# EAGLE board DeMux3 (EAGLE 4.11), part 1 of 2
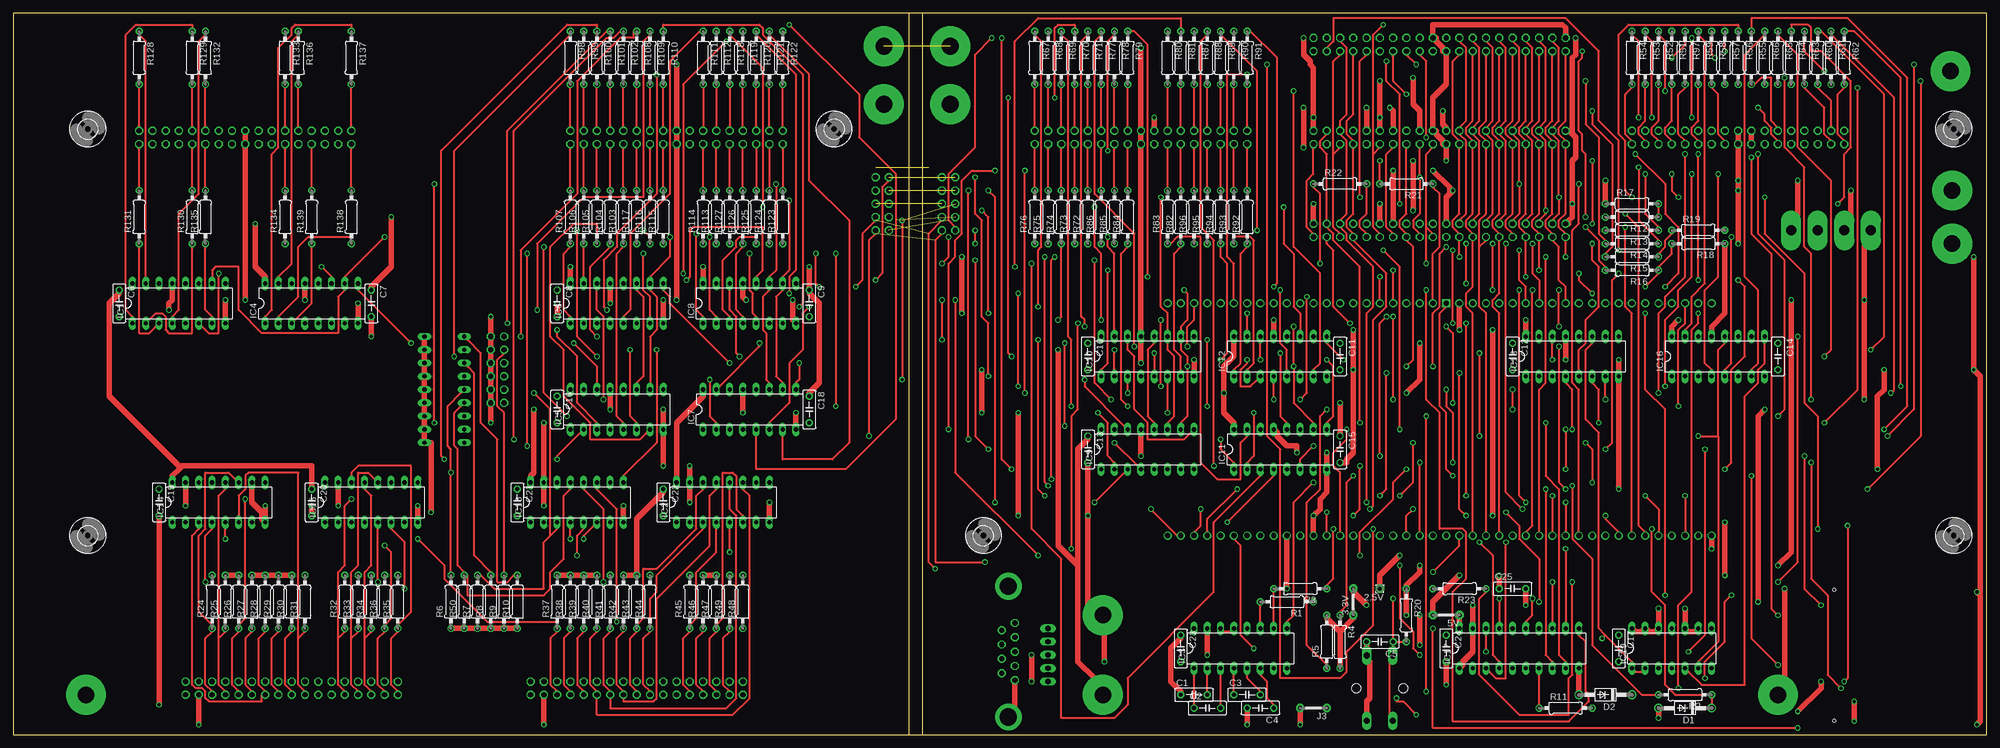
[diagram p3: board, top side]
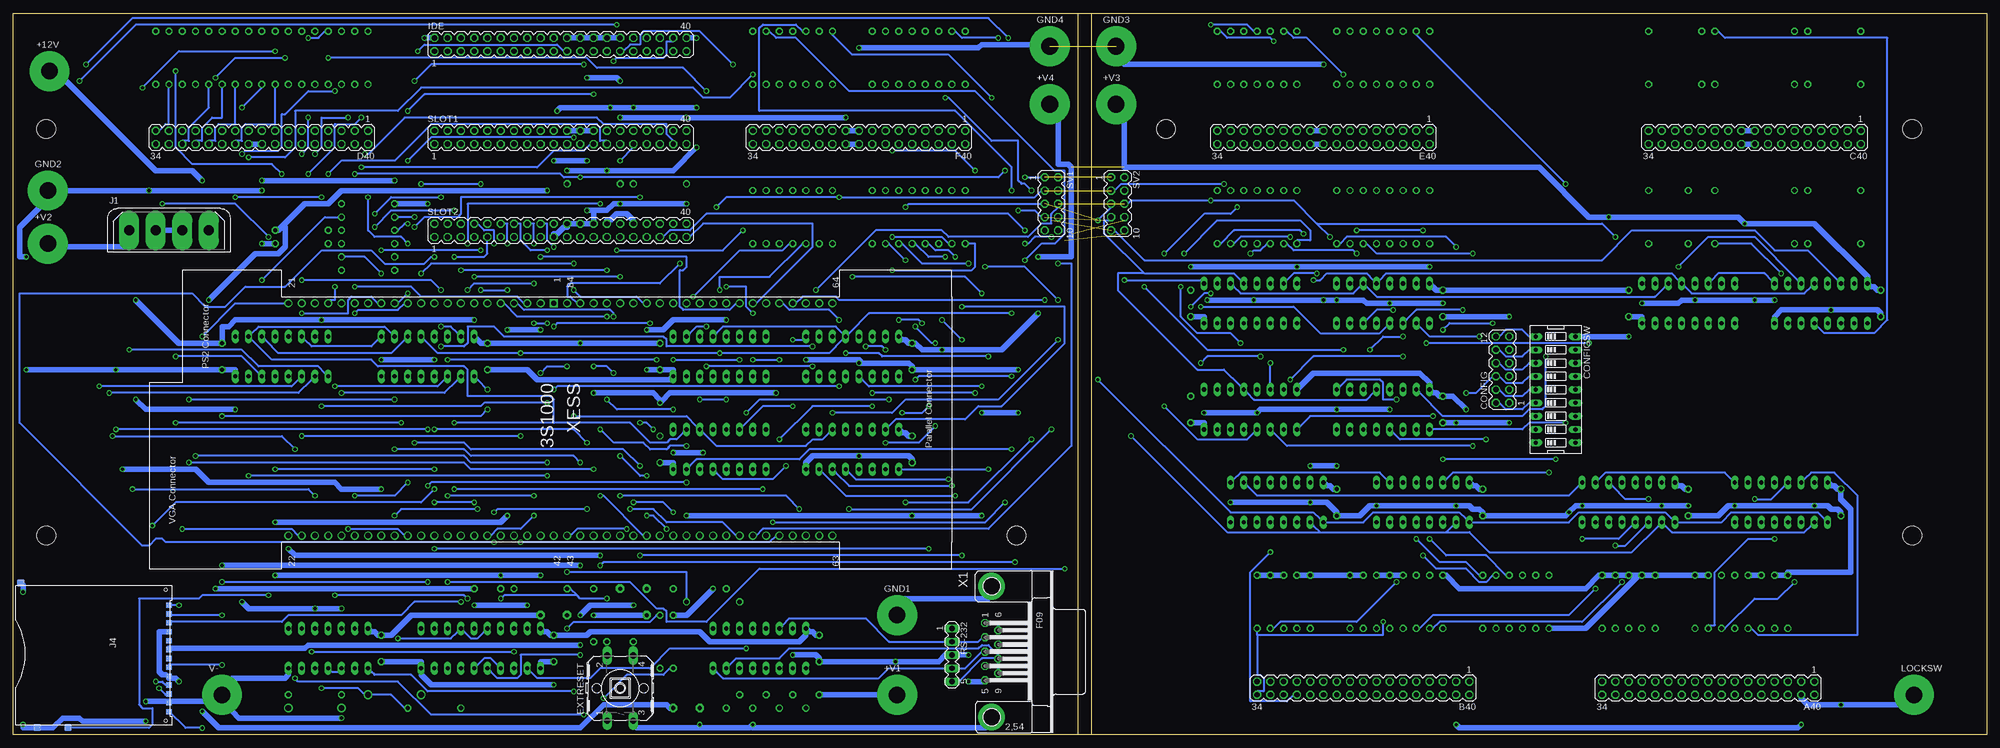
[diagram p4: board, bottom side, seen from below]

Size 377.82 x 138.11 mm. Coordinates in mm from the lower left corner, seen from the top.
Outline: 377.82,138.11 377.82,0 174.62,0 171.45,0
Outline: 377.82,138.11 173.99,138.11
Outline: 173.99,138.11 173.04,138.11
Outline: 173.04,138.11 171.45,138.11
Outline: 171.45,138.11 0,138.11 0,0 171.45,0
Outline: 377.82,138.11 173.99,138.11
Outline: 173.99,138.11 173.04,138.11
Outline: 171.45,138.11 171.45,0
Outline: 173.99,138.11 173.99,0
Copper layers (1*16): Top 0.035mm / dielectric 1.5mm / Bottom 0.035mm
Design rules "15mils": minimum track width 15mil, minimum drill 24mil, track to track 15mil, track to pad 10mil, pad to pad 10mil, via to via 10mil, smd to smd 10mil, copper to edge 25mil, drill to drill 10mil, minimum pad ring 10mil, minimum via ring 8mil, stop-mask expansion 0mil, vias tented up to drill 0mil, thermal gap 10mil
Net classes: 1 supply: width 1.016 mm

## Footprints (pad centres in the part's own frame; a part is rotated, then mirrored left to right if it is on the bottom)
1,6/0,8 = drill 0.813 pad 1.6 octagon: 1 0,0
05 = drill 0.813 pad 1.6 octagon: 1 -2.54,0; 2 2.54,0
SPADELUG = drill 3.175 pad 7.62 round: 1 0,0
MA17-2 = drill 1.016 octagon: 1 -20.32,-1.27; 2 -20.32,1.27; 3 -17.78,-1.27; 4 -17.78,1.27; 5 -15.24,-1.27; 6 -15.24,1.27; 7 -12.7,-1.27; 8 -12.7,1.27; 9 -10.16,-1.27; 10 -10.16,1.27; 11 -7.62,-1.27; 12 -7.62,1.27; 13 -5.08,-1.27; 14 -5.08,1.27; 15 -2.54,-1.27; 16 -2.54,1.27; 17 0,-1.27; 18 0,1.27; 19 2.54,-1.27; 20 2.54,1.27; 21 5.08,-1.27; 22 5.08,1.27; 23 7.62,-1.27; 24 7.62,1.27; 25 10.16,-1.27; 26 10.16,1.27; 27 12.7,-1.27; 28 12.7,1.27; 29 15.24,-1.27; 30 15.24,1.27; 31 17.78,-1.27; 32 17.78,1.27; 33 20.32,-1.27; 34 20.32,1.27
C050-025X075 = drill 0.813 octagon: 1 -2.54,0; 2 2.54,0
MA06-2 = drill 1.016 octagon: 1 -6.35,-1.27; 2 -6.35,1.27; 3 -3.81,-1.27; 4 -3.81,1.27; 5 -1.27,-1.27; 6 -1.27,1.27; 7 1.27,-1.27; 8 1.27,1.27; 9 3.81,-1.27; 10 3.81,1.27; 11 6.35,-1.27; 12 6.35,1.27
EDG-09 = drill 0.813 long: 1 -10.16,-3.81; 2 -7.62,-3.81; 3 -5.08,-3.81; 4 -2.54,-3.81; 5 0,-3.81; 6 2.54,-3.81; 7 5.08,-3.81; 8 7.62,-3.81; 9 10.16,-3.81; 10 10.16,3.81; 11 7.62,3.81; 12 5.08,3.81; 13 2.54,3.81; 14 0,3.81; 15 -2.54,3.81; 16 -5.08,3.81; 17 -7.62,3.81; 18 -10.16,3.81
DO41Z10 = drill 1.118 round: A 5.08,0; C -5.08,0
B3F-40XX = drill 1.194 long: 1 -6.248,2.489; 2 6.248,2.489; 3 -6.248,-2.489; 4 6.248,-2.489 | hole 1.803: 0,-4.496; 0,4.496
DIL16 = drill 0.813 long: 1 -8.89,-3.81; 2 -6.35,-3.81; 3 -3.81,-3.81; 4 -1.27,-3.81; 5 1.27,-3.81; 6 3.81,-3.81; 7 6.35,-3.81; 8 8.89,-3.81; 9 8.89,3.81; 10 6.35,3.81; 11 3.81,3.81; 12 1.27,3.81; 13 -1.27,3.81; 14 -3.81,3.81; 15 -6.35,3.81; 16 -8.89,3.81
DIL20 = drill 0.813 long: 1 -11.43,-3.81; 2 -8.89,-3.81; 3 -6.35,-3.81; 4 -3.81,-3.81; 5 -1.27,-3.81; 6 1.27,-3.81; 7 3.81,-3.81; 8 6.35,-3.81; 9 8.89,-3.81; 10 11.43,-3.81; 11 11.43,3.81; 12 8.89,3.81; 13 6.35,3.81; 14 3.81,3.81; 15 1.27,3.81; 16 -1.27,3.81; 17 -3.81,3.81; 18 -6.35,3.81; 19 -8.89,3.81; 20 -11.43,3.81
DIL14 = drill 0.813 long: 1 -7.62,-3.81; 2 -5.08,-3.81; 3 -2.54,-3.81; 4 0,-3.81; 5 2.54,-3.81; 6 5.08,-3.81; 7 7.62,-3.81; 8 7.62,3.81; 9 5.08,3.81; 10 2.54,3.81; 11 0,3.81; 12 -2.54,3.81; 13 -5.08,3.81; 14 -7.62,3.81
MA20-2 = drill 1.016 octagon: 1 -24.13,-1.27; 2 -24.13,1.27; 3 -21.59,-1.27; 4 -21.59,1.27; 5 -19.05,-1.27; 6 -19.05,1.27; 7 -16.51,-1.27; 8 -16.51,1.27; 9 -13.97,-1.27; 10 -13.97,1.27; 11 -11.43,-1.27; 12 -11.43,1.27; 13 -8.89,-1.27; 14 -8.89,1.27; 15 -6.35,-1.27; 16 -6.35,1.27; 17 -3.81,-1.27; 18 -3.81,1.27; 19 -1.27,-1.27; 20 -1.27,1.27; 21 1.27,-1.27; 22 1.27,1.27; 23 3.81,-1.27; 24 3.81,1.27; 25 6.35,-1.27; 26 6.35,1.27; 27 8.89,-1.27; 28 8.89,1.27; 29 11.43,-1.27; 30 11.43,1.27; 31 13.97,-1.27; 32 13.97,1.27; 33 16.51,-1.27; 34 16.51,1.27; 35 19.05,-1.27; 36 19.05,1.27; 37 21.59,-1.27; 38 21.59,1.27; 39 24.13,-1.27; 40 24.13,1.27
FLOPPY-4 = drill 1.93 pad 3.81 long: 1 7.62,0; 2 2.54,0; 3 -2.54,0; 4 -7.62,0
SCDA5A = smd 1 x 1.3: 1 -7.525,-0.65; 2 -5.825,-0.65; 3 -4.125,-0.65; 3A -2.425,-0.65; 4 -0.725,-0.65; 4A 0.975,-0.65; 5 2.675,-0.65; 6 4.375,-0.65; 7 6.075,-0.65; 8 7.775,-0.65; 9 -9.225,-0.65; 10 11.175,-0.65; 11 9.475,-0.65 | smd 1.4 x 1.4: 12 14.2,-19.955; 13 14.2,-25.875; 14 -13.475,-28.975 | hole 0.61: 12.875,-1.235; -12.125,-1.235
0207/10 = drill 0.813 octagon: 1 -5.08,0; 2 5.08,0
MA05-1 = drill 1.016 long: 1 -5.08,0; 2 -2.54,0; 3 0,0; 4 2.54,0; 5 5.08,0
MA05-2 = drill 1.016 octagon: 1 -5.08,-1.27; 2 -5.08,1.27; 3 -2.54,-1.27; 4 -2.54,1.27; 5 0,-1.27; 6 0,1.27; 7 2.54,-1.27; 8 2.54,1.27; 9 5.08,-1.27; 10 5.08,1.27
3,6 = hole 3.6: 0,0
F09HP = drill 1.016 octagon: 1 -5.486,-1.27; 2 -2.743,-1.27; 3 0,-1.27; 4 2.743,-1.27; 5 5.486,-1.27; 6 -4.115,1.27; 7 -1.372,1.27; 8 1.372,1.27; 9 4.115,1.27 | drill 3.302 pad 5.08 round: G1 -12.522,0; G2 12.522,0
3S1000 = drill 1.016 square: 1 0,0 | drill 1.016 round: 2 0,-2.54; 3 0,-5.08; 4 0,-7.62; 5 0,-10.16; 6 0,-12.7; 7 0,-15.24; 8 0,-17.78; 9 0,-20.32; 10 0,-22.86; 11 0,-25.4; 12 0,-27.94; 13 0,-30.48; 14 0,-33.02; 15 0,-35.56; 16 0,-38.1; 17 0,-40.64; 18 0,-43.18; 19 0,-45.72; 20 0,-48.26; 21 0,-50.8; 22 44.45,-50.8; 23 44.45,-48.26; 24 44.45,-45.72; 25 44.45,-43.18; 26 44.45,-40.64; 27 44.45,-38.1; 28 44.45,-35.56; 29 44.45,-33.02; 30 44.45,-30.48; 31 44.45,-27.94; 32 44.45,-25.4; 33 44.45,-22.86; 34 44.45,-20.32; 35 44.45,-17.78; 36 44.45,-15.24; 37 44.45,-12.7; 38 44.45,-10.16; 39 44.45,-7.62; 40 44.45,-5.08; 41 44.45,-2.54; 42 44.45,0; 43 44.45,2.54; 44 44.45,5.08; 45 44.45,7.62; 46 44.45,10.16; 47 44.45,12.7; 48 44.45,15.24; 49 44.45,17.78; 50 44.45,20.32; 51 44.45,22.86; 52 44.45,25.4; 53 44.45,27.94; 54 44.45,30.48; 55 44.45,33.02; 56 44.45,35.56; 57 44.45,38.1; 58 44.45,40.64; 59 44.45,43.18; 60 44.45,45.72; 61 44.45,48.26; 62 44.45,50.8; 63 44.45,53.34; 64 0,53.34; 65 0,50.8; 66 0,48.26; 67 0,45.72; 68 0,43.18; 69 0,40.64; 70 0,38.1; 71 0,35.56; 72 0,33.02; 73 0,30.48; 74 0,27.94; 75 0,25.4; 76 0,22.86; 77 0,20.32; 78 0,17.78; 79 0,15.24; 80 0,12.7; 81 0,10.16; 82 0,7.62; 83 0,5.08; 84 0,2.54

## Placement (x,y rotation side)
2.5V  [1,6/0,8]  261.62,27.94 180 top
3.3V  J5MM  [05]  256.54,25.4 90 top
5V  J5MM  [05]  274.32,22.86 180 top
+12V  LUG  [SPADELUG]  370.84,127 0 bottom
+V1  LUG  [SPADELUG]  208.6,7.62 0 bottom
+V2  LUG  [SPADELUG]  371.16,93.98 0 bottom
+V3  LUG  [SPADELUG]  166.69,120.65 0 bottom
+V4  LUG  [SPADELUG]  179.39,120.65 0 bottom
A40  [MA17-2]  53.34,8.89 180 bottom
B40  [MA17-2]  119.38,8.89 180 bottom
C1  0.1uf  [C050-025X075]  226.06,7.62 0 top
C2  0.1uf  [C050-025X075]  228.6,5.08 0 top
C3  0.1uf  [C050-025X075]  236.22,7.62 0 top
C4  0.1uf  [C050-025X075]  238.76,5.08 180 top
C5  0.1uf  [C050-025X075]  261.62,17.78 180 top
C6  0.1uf  [C050-025X075]  20.32,82.55 270 top
C7  0.1uf  [C050-025X075]  68.58,82.55 270 top
C8  0.1uf  [C050-025X075]  104.14,82.55 270 top
C9  0.1uf  [C050-025X075]  152.4,82.55 270 top
C10  0.1uf  [C050-025X075]  205.74,72.39 270 top
C11  0.1uf  [C050-025X075]  254,72.39 270 top
C12  0.1uf  [C050-025X075]  287.02,72.39 270 top
C13  0.1uf  [C050-025X075]  205.74,54.61 270 top
C14  0.1uf  [C050-025X075]  337.82,72.39 270 top
C15  0.1uf  [C050-025X075]  254,54.61 270 top
C16  0.1uf  [C050-025X075]  104.14,62.23 270 top
C17  0.1uf  [C050-025X075]  307.34,16.51 270 top
C18  0.1uf  [C050-025X075]  152.4,62.23 270 top
C19  0.1uf  [C050-025X075]  27.94,44.45 270 top
C20  0.1uf  [C050-025X075]  57.15,44.45 270 top
C21  0.1uf  [C050-025X075]  96.52,44.45 270 top
C22  0.1uf  [C050-025X075]  124.46,44.45 270 top
C23  0.1uf  [C050-025X075]  223.52,16.51 270 top
C24  0.1uf  [C050-025X075]  274.32,16.51 270 top
C25  0.1uf  [C050-025X075]  287.02,27.94 0 top
C40  [MA17-2]  44.45,114.3 180 bottom
CONFIG  [MA06-2]  92.71,69.85 90 bottom
CONFIGSW  [EDG-09]  82.55,66.04 270 bottom
D1  1N4728  [DO41Z10]  320.04,5.08 180 top
D2  1N4728  [DO41Z10]  304.8,7.62 180 top
D40  [MA17-2]  330.2,114.3 180 bottom
E40  [MA17-2]  127,114.3 180 bottom
EXTRESET  [B3F-40XX]  261.62,8.89 90 bottom
F40  [MA17-2]  215.9,114.3 180 bottom
GND1  LUG  [SPADELUG]  208.6,22.86 0 bottom
GND2  LUG  [SPADELUG]  371.16,104.14 0 bottom
GND3  LUG  [SPADELUG]  166.69,131.76 0 bottom
GND4  LUG  [SPADELUG]  179.39,131.76 0 bottom
IC1  74HC595N  [DIL16]  31.75,82.55 0 top
IC2  74HC165N  [DIL16]  135.89,44.45 0 top
IC3  MAX232A  [DIL16]  234.95,16.51 0 top
IC4  74HC595N  [DIL16]  57.15,82.55 0 top
IC5  74HC595N  [DIL16]  115.57,62.23 0 top
IC6  74HC595N  [DIL16]  115.57,82.55 0 top
IC7  74HC595N  [DIL16]  140.97,62.23 0 top
IC8  74HC595N  [DIL16]  140.97,82.55 0 top
IC9  74HC595N  [DIL16]  217.17,54.61 0 top
IC10  74HC595N  [DIL16]  217.17,72.39 0 top
IC11  74HC595N  [DIL16]  242.57,54.61 0 top
IC12  74HC595N  [DIL16]  242.57,72.39 0 top
IC13  74HC595N  [DIL16]  298.45,72.39 0 top
IC14  74HC165N  [DIL16]  39.37,44.45 0 top
IC15  74HC165N  [DIL16]  68.58,44.45 0 top
IC16  74HC595N  [DIL16]  326.39,72.39 0 top
IC17  74HCT244N  [DIL20]  288.29,16.51 0 top
IC18  74HC165N  [DIL16]  107.95,44.45 0 top
IC19  74ALS00N  [DIL14]  317.5,16.51 0 top
IDE  [MA20-2]  273.05,132.08 0 bottom
J1  [FLOPPY-4]  347.98,96.52 0 bottom
J3  J5MM  [05]  248.92,5.08 180 top
J4  SDCARD  [SCDA5A]  347.35,15.56 270 bottom
LOCKSW  LUG  [SPADELUG]  13.97,7.62 0 bottom
R1  330  [0207/10]  243.84,25.4 180 top
R2  330  [0207/10]  320.04,7.62 180 top
R3  330  [0207/10]  246.38,27.94 180 top
R4  330  [0207/10]  254,17.78 270 top
R5  330  [0207/10]  251.46,17.78 90 top
R6  3K  [0207/10]  83.82,25.4 90 top
R7  3K  [0207/10]  88.9,25.4 90 top
R8  3K  [0207/10]  91.44,25.4 90 top
R9  3K  [0207/10]  93.98,25.4 90 top
R10  3K  [0207/10]  96.52,25.4 90 top
R11  330  [0207/10]  297.18,5.08 0 top
R12  330  [0207/10]  309.88,99.06 180 top
R13  47  [0207/10]  309.88,96.52 180 top
R14  47  [0207/10]  309.88,93.98 180 top
R15  330  [0207/10]  309.88,91.44 180 top
R16  330  [0207/10]  309.88,88.9 180 top
R17  10K  [0207/10]  309.88,101.6 0 top
R18  10K  [0207/10]  322.58,93.98 180 top
R19  10K  [0207/10]  322.58,96.52 0 top
R20  4.7K  [0207/10]  266.7,22.86 270 top
R21  330  [0207/10]  266.7,105.41 180 top
R22  330  [0207/10]  254,105.41 0 top
R23  330  [0207/10]  276.86,27.94 180 top
R24  3K  [0207/10]  38.1,25.4 90 top
R25  3K  [0207/10]  40.64,25.4 90 top
R26  3K  [0207/10]  43.18,25.4 90 top
R27  3K  [0207/10]  45.72,25.4 90 top
R28  3K  [0207/10]  48.26,25.4 90 top
R29  3K  [0207/10]  50.8,25.4 90 top
R30  3K  [0207/10]  53.34,25.4 90 top
R31  3K  [0207/10]  55.88,25.4 90 top
R32  3K  [0207/10]  63.5,25.4 90 top
R33  3K  [0207/10]  66.04,25.4 90 top
R34  3K  [0207/10]  68.58,25.4 90 top
R35  3K  [0207/10]  73.66,25.4 90 top
R36  3K  [0207/10]  71.12,25.4 90 top
R37  3K  [0207/10]  104.14,25.4 90 top
R38  3K  [0207/10]  106.68,25.4 90 top
R39  3K  [0207/10]  109.22,25.4 90 top
R40  3K  [0207/10]  111.76,25.4 90 top
R41  3K  [0207/10]  114.3,25.4 90 top
R42  3K  [0207/10]  116.84,25.4 90 top
R43  3K  [0207/10]  119.38,25.4 90 top
R44  3K  [0207/10]  121.92,25.4 90 top
R45  3K  [0207/10]  129.54,25.4 90 top
R46  3K  [0207/10]  132.08,25.4 90 top
R47  3K  [0207/10]  134.62,25.4 90 top
R48  3K  [0207/10]  139.7,25.4 90 top
R49  3K  [0207/10]  137.16,25.4 90 top
R50  3K  [0207/10]  86.36,25.4 90 top
R51  [0207/10]  317.5,129.54 270 top
R52  [0207/10]  314.96,129.54 270 top
R53  [0207/10]  312.42,129.54 270 top
R54  [0207/10]  309.88,129.54 270 top
R55  [0207/10]  332.74,129.54 270 top
R56  [0207/10]  330.2,129.54 270 top
R57  [0207/10]  327.66,129.54 270 top
R58  3K  [0207/10]  325.12,129.54 270 top
R59  [0207/10]  322.58,129.54 270 top
R60  [0207/10]  345.44,129.54 270 top
R61  [0207/10]  347.98,129.54 270 top
R62  [0207/10]  350.52,129.54 270 top
R63  [0207/10]  342.9,129.54 270 top
R64  [0207/10]  340.36,129.54 270 top
R65  [0207/10]  337.82,129.54 270 top
R66  3K  [0207/10]  335.28,129.54 270 top
R67  [0207/10]  195.58,129.54 270 top
R68  [0207/10]  198.12,129.54 270 top
R69  [0207/10]  200.66,129.54 270 top
R70  [0207/10]  203.2,129.54 270 top
R71  [0207/10]  205.74,129.54 270 top
R72  [0207/10]  205.74,99.06 90 top
R73  [0207/10]  203.2,99.06 90 top
R74  3K  [0207/10]  200.66,99.06 90 top
R75  [0207/10]  198.12,99.06 90 top
R76  [0207/10]  195.58,99.06 90 top
R77  [0207/10]  208.28,129.54 270 top
R78  [0207/10]  210.82,129.54 270 top
R79  [0207/10]  213.36,129.54 270 top
R80  [0207/10]  220.98,129.54 270 top
R81  [0207/10]  223.52,129.54 270 top
R82  3K  [0207/10]  223.52,99.06 90 top
R83  [0207/10]  220.98,99.06 90 top
R84  [0207/10]  213.36,99.06 90 top
R85  [0207/10]  210.82,99.06 90 top
R86  [0207/10]  208.28,99.06 90 top
R87  [0207/10]  226.06,129.54 270 top
R88  [0207/10]  228.6,129.54 270 top
R89  [0207/10]  231.14,129.54 270 top
R90  3K  [0207/10]  233.68,129.54 270 top
R91  [0207/10]  236.22,129.54 270 top
R92  [0207/10]  236.22,99.06 90 top
R93  [0207/10]  233.68,99.06 90 top
R94  [0207/10]  231.14,99.06 90 top
R95  [0207/10]  228.6,99.06 90 top
R96  [0207/10]  226.06,99.06 90 top
R97  3K  [0207/10]  320.04,129.54 270 top
R98  [0207/10]  106.68,129.54 270 top
R99  [0207/10]  109.22,129.54 270 top
R100  [0207/10]  111.76,129.54 270 top
R101  [0207/10]  114.3,129.54 270 top
R102  [0207/10]  116.84,129.54 270 top
R103  [0207/10]  116.84,99.06 90 top
R104  [0207/10]  114.3,99.06 90 top
R105  3K  [0207/10]  111.76,99.06 90 top
R106  [0207/10]  109.22,99.06 90 top
R107  [0207/10]  106.68,99.06 90 top
R108  [0207/10]  119.38,129.54 270 top
R109  [0207/10]  121.92,129.54 270 top
R110  [0207/10]  124.46,129.54 270 top
R111  [0207/10]  132.08,129.54 270 top
R112  [0207/10]  134.62,129.54 270 top
R113  3K  [0207/10]  134.62,99.06 90 top
R114  [0207/10]  132.08,99.06 90 top
R115  [0207/10]  124.46,99.06 90 top
R116  [0207/10]  121.92,99.06 90 top
R117  [0207/10]  119.38,99.06 90 top
R118  [0207/10]  137.16,129.54 270 top
R119  [0207/10]  139.7,129.54 270 top
R120  [0207/10]  142.24,129.54 270 top
R121  3K  [0207/10]  144.78,129.54 270 top
R122  [0207/10]  147.32,129.54 270 top
R123  [0207/10]  147.32,99.06 90 top
R124  [0207/10]  144.78,99.06 90 top
R125  [0207/10]  142.24,99.06 90 top
R126  [0207/10]  139.7,99.06 90 top
R127  3K  [0207/10]  137.16,99.06 90 top
R128  [0207/10]  24.13,129.54 270 top
R129  [0207/10]  34.29,129.54 270 top
R130  [0207/10]  34.29,99.06 90 top
R131  [0207/10]  24.13,99.06 90 top
R132  [0207/10]  36.83,129.54 270 top
R133  [0207/10]  52.07,129.54 270 top
R134  [0207/10]  52.07,99.06 90 top
R135  3K  [0207/10]  36.83,99.06 90 top
R136  [0207/10]  54.61,129.54 270 top
R137  [0207/10]  64.77,129.54 270 top
R138  [0207/10]  64.77,99.06 90 top
R139  3K  [0207/10]  57.15,99.06 90 top
RS-232  [MA05-1]  198.12,15.24 270 bottom
SLOT1  [MA20-2]  273.05,114.3 0 bottom
SLOT2  [MA20-2]  273.05,96.52 0 bottom
SV1  [MA05-2]  179.07,101.6 270 bottom
SV2  [MA05-2]  166.37,101.6 270 bottom
U$5  [3,6]  371.48,115.89 0 top
U$6  [3,6]  371.48,38.1 0 top
U$7  [3,6]  185.74,38.1 0 top
U$8  [3,6]  14.29,38.1 0 top
U$9  [3,6]  14.29,115.89 0 top
U$11  [3,6]  157.16,115.89 0 top
V-  LUG  [SPADELUG]  337.82,7.62 0 bottom
X1  [F09HP]  190.5,15.88 270 bottom
XESS  3S1000  [3S1000]  274.32,82.55 270 bottom

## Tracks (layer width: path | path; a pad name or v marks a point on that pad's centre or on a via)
3S-LCL\  (via drill 0.61)
  Top 0.381: v270.51,85.09 270.51,64.14 273.05,61.59 273.05,39.37 277.5,39.37 278.13,38.73 278.13,29.84 275.59,27.3 275.59,2.54 297.81,2.54 301.62,6.35 301.62,7.62 300.99,8.26 300.99,17.78 299.72,19.05 IC17.11
  Bottom 0.381: v270.51,85.09 269.24,83.82 258.44,83.82 257.18,82.55 XESS.78
3S-LCLK  (via drill 0.61)
  Top 0.381: v280.67,36.83 283.21,34.29 283.21,15.24 284.48,13.97 IC17.4
  Bottom 0.381: IC17.4 285.12,13.34 286.38,14.61 287.65,14.61 288.93,13.34 IC17.6 | v280.67,36.83 233.04,36.83 231.78,38.1 XESS.59
3S-LSER  (via drill 0.61)
  Top 0.381: v237.49,16.51 234.95,19.05 234.95,36.2 233.68,37.47 XESS.58
  Bottom 0.381: v237.49,16.51 252.09,16.51 255.91,12.7 265.43,12.7 267.33,10.79 277.5,10.79 278.76,12.06 IC17.2
3S-SCL\  (via drill 0.61)
  Top 0.381: v293.37,46.99 293.37,15.24 294.64,13.97 IC17.8 | v234.31,46.99 228.6,41.27 228.6,38.73 XESS.60
  Bottom 0.381: v234.31,46.99 v293.37,46.99
3S-SCLK  (via drill 0.61)
  Top 0.381: v290.83,26.04 290.83,22.86 289.56,21.59 IC17.15 | v316.23,26.67 316.23,62.23 312.42,66.04 v312.42,80.64
  Bottom 0.381: v290.83,26.04 291.46,26.67 v316.23,26.67 | v312.42,80.64 311.79,81.28 304.17,81.28 302.89,82.55 XESS.12
3S-SSER  (via drill 0.61)
  Top 0.381: v322.58,80.64 322.58,78.74 321.31,77.47 321.31,27.3 318.77,24.77 v318.77,8.89
  Bottom 0.381: R11.2 302.89,5.08 305.44,7.62 309.25,7.62 D2.C 310.51,7.62 311.79,8.89 v318.77,8.89 | v322.58,80.64 313.69,80.64 313.69,83.19 313.06,83.82 309.25,83.82 307.98,82.55 XESS.14
+2V5  (via drill 0.61)
  Top 1.016: v325.12,35.56 325.12,37.47 XESS.22 | v265.43,34.29 261.62,30.48 261.62,28.57 2.5V.1
  Bottom 1.016: v325.12,35.56 323.85,34.29 v265.43,34.29
+3V3  (via drill 0.61)
  Top 1.016: v266.7,22.86 266.7,27.3 R20.1 266.7,28.57 269.24,31.11 v269.24,32.38 | 254,19.68 251.46,22.23 R5.2 | 254,19.68 254,13.34 R4.2 | v243.84,27.94 243.84,37.47 XESS.54 | 254,19.68 256.54,22.23 3.3V.1 | v259.08,120.02 259.08,116.2 SLOT1.32 | v263.52,120.02 264.16,119.38 264.16,116.2 SLOT1.28 | v273.69,119.38 273.69,116.84 274.32,116.2 SLOT1.20 | 275.27,103.82 274.32,102.87 274.32,98.42 SLOT2.20 | v275.59,104.14 275.27,103.82 | v264.16,107.95 264.16,98.42 SLOT2.28 | v271.78,107.95 274.95,104.78 274.95,104.14 275.27,103.82 | v247.01,112.39 v247.01,120.02 | v337.82,32.38 340.36,34.92 v340.36,83.19
  Bottom 1.016: v266.7,22.86 257.18,22.86 3.3V.1 | v243.84,27.94 248.92,22.86 250.82,22.86 R5.2 | v273.69,119.38 273.05,120.02 v263.52,120.02 v259.08,120.02 v247.01,120.02 | SLOT2.32 259.08,98.42 260.35,99.69 262.25,99.69 263.52,98.42 264.16,98.42 SLOT2.28 | 326.07,97.47 321.94,101.6 317.5,101.6 314.96,104.14 v275.59,104.14 | 326.07,97.47 327.02,96.52 R19.2 | v271.78,107.95 v264.16,107.95 251.46,107.95 v247.01,112.39 | v269.24,32.38 v337.82,32.38 | v340.36,83.19 331.47,92.08 327.02,92.08 325.75,93.34 325.75,97.16 326.07,97.47
+5V  (via drill 0.61)
  Top 1.016: v284.48,30.48 284.48,28.57 C25.1 | v276.86,30.48 271.78,25.4 271.78,23.5 5V.2 | v276.86,77.47 276.86,81.92 XESS.2 | v283.21,41.91 v283.21,77.47 | v327.66,30.48 v327.66,40.64
  Bottom 1.016: v276.86,30.48 v284.48,30.48 v327.66,30.48 | v283.21,77.47 v276.86,77.47 | v283.21,41.91 284.48,40.64 v327.66,40.64
+12V  (via drill 0.61)
  Top 1.016: v341.63,106.05 341.63,99.69 J1.1
  Bottom 1.016: v341.63,106.05 343.54,107.95 350.52,107.95 367.67,125.09 +12V.1
AC0
  Top 0.381: R101.2 114.3,123.83 114.3,116.2 E40.7
AC1
  Top 0.381: R106.2 109.22,104.78 109.22,112.39 E40.4
AC2
  Top 0.381: R111.2 132.08,123.83 132.08,116.2 E40.21
AC3
  Top 0.381: R116.2 121.92,104.78 121.92,112.39 E40.14
AC4
  Top 0.381: R121.2 144.78,123.83 144.78,116.2 E40.31
AC5
  Top 0.381: R126.2 139.7,104.78 139.7,112.39 E40.28
AC6
  Top 0.381: R70.2 203.2,123.83 203.2,116.2 F40.7
AC7
  Top 0.381: R75.2 198.12,104.78 198.12,112.39 F40.4
AC8
  Top 0.381: R80.2 220.98,123.83 220.98,116.2 F40.21
AC9
  Top 0.381: R85.2 210.82,104.78 210.82,112.39 F40.14
AC10
  Top 0.381: R90.2 233.68,123.83 233.68,116.2 F40.31
AC11
  Top 0.381: R95.2 228.6,104.78 228.6,112.39 F40.28
AND
  Top 0.381: R54.2 309.88,123.83 308.61,122.56 308.61,114.94 309.88,113.67 D40.2
BREAK
  Bottom 0.381: R57.2 327.66,123.83 327.66,116.84 333.38,116.84 334.01,116.2 334.01,113.67 335.28,113.67 D40.22
CA
  Top 0.381: R63.2 342.9,123.83 346.71,120.02 346.71,114.94 347.98,113.67 D40.32
CF1
  Top 0.381: CONFIGSW.6 85.72,62.87 84.45,61.59 84.45,55.24 85.09,54.61 85.09,32.38 86.36,31.11 R50.2 87,30.48 87,26.67 101.6,26.67 102.87,27.94 102.87,31.11 105.41,33.66 105.41,45.72 106.68,46.99 IC18.13
  Bottom 0.381: CONFIG.2 93.34,63.5 92.08,62.23 88.9,62.23 87.63,63.5 CONFIGSW.6
CF2  (via drill 0.61)
  Top 0.381: R6.2 83.82,31.11 v83.82,50.16 83.82,54.61 83.19,55.24 83.19,62.87 85.72,65.41 CONFIGSW.5
  Bottom 0.381: v83.82,50.16 102.23,50.16 103.5,48.9 IC18.14 | CONFIG.4 93.34,66.04 92.08,64.77 88.9,64.77 87.63,66.04 CONFIGSW.5
CF3  (via drill 0.61)
  Top 0.381: 102.87,38.1 104.14,39.37 IC18.3 | 102.87,38.1 101.6,36.83 101.6,27.94 92.08,27.94 89.53,30.48 R7.2 | v99.69,65.41 102.87,62.23 102.87,38.1
  Bottom 0.381: CONFIGSW.4 87.63,68.58 88.9,67.31 92.08,67.31 93.34,68.58 CONFIG.6 94.61,68.58 97.79,65.41 v99.69,65.41
CF4  (via drill 0.61)
  Top 0.381: R8.2 91.44,31.11 88.27,34.29 88.27,69.22 87,70.48 CONFIGSW.3 | v106.68,37.47 106.68,39.37 IC18.4
  Bottom 0.381: v106.68,37.47 103.5,34.29 95.89,34.29 92.08,30.48 R8.2 | CONFIG.8 93.34,71.12 92.08,69.85 88.9,69.85 87.63,71.12 CONFIGSW.3
CF5  (via drill 0.61)
  Top 0.381: R9.2 93.98,31.11 93.98,61.59 92.71,62.87 92.71,71.75 93.98,73.03 CONFIG.10 | v107.95,34.29 107.95,38.1 109.22,39.37 IC18.5
  Bottom 0.381: v107.95,34.29 105.41,31.75 99.69,31.75 97.16,29.21 95.89,29.21 94.61,30.48 R9.2 | CONFIGSW.2 87.63,73.66 88.9,72.39 92.08,72.39 93.34,73.66 CONFIG.10
CF6  (via drill 0.61)
  Top 0.381: R10.2 95.89,30.48 94.61,29.21 92.71,29.21 92.71,56.52 89.53,59.69 89.53,73.03 87,75.56 CONFIGSW.1 | v109.22,37.47 109.22,38.1 111.12,40.01 IC18.6
  Bottom 0.381: v109.22,37.47 104.78,33.02 99.69,33.02 97.16,30.48 R10.2 | CONFIG.12 93.34,76.2 92.08,77.47 88.9,77.47 87.63,76.2 CONFIGSW.1
CLK  (via drill 0.61)
  Top 0.381: 270.51,97.16 271.78,95.89 SLOT2.21 | 270.51,97.16 270.51,111.12 271.78,112.39 SLOT1.21 | v302.26,84.45 299.72,87 v299.72,88.27 | v270.51,90.17 270.51,97.16
  Bottom 0.381: v302.26,84.45 304.17,82.55 XESS.13 | v299.72,88.27 297.81,90.17 v270.51,90.17
CONT  (via drill 0.61)
  Top 0.381: R46.1 132.08,19.68 130.81,18.41 130.81,9.53 132.08,8.26 B40.28 | v137.16,34.92 137.16,39.37 IC2.5
  Bottom 0.381: v137.16,34.92 140.97,31.11 140.97,6.35 133.99,6.35 132.72,7.62 B40.28
DCA
  Top 0.381: R51.2 317.5,123.83 317.5,117.47 316.23,116.2 316.23,114.94 317.5,113.67 D40.8
DEFER
  Bottom 0.381: R66.2 335.28,123.83 335.28,116.84 338.45,116.84 339.09,116.2 339.09,113.67 340.36,113.67 D40.26
DEP
  Top 0.381: B40.20 121.92,8.26 120.65,9.53 120.65,18.41 121.92,19.68 R44.1 121.92,20.95 121.92,26.04 123.19,27.3 123.19,30.48 132.08,39.37 IC2.3
DF0
  Top 0.381: R128.2 24.13,123.83 24.13,116.2 C40.1
DF1
  Top 0.381: R130.2 34.29,104.78 34.29,112.39 C40.10
DF2
  Top 0.381: R132.2 36.83,123.83 36.83,116.2 C40.11
EXAM
  Top 0.381: B40.26 129.54,8.26 128.27,9.53 128.27,18.41 129.54,19.68 R45.1 129.54,20.95 130.81,22.23 130.81,31.11 134.62,34.92 134.62,39.37 IC2.4
EXECUTE
  Bottom 0.381: R65.2 337.82,123.83 337.82,118.11 339.73,118.11 341.63,116.2 341.63,113.67 342.9,113.67 D40.28
FETCH  (via drill 0.61)
  Top 0.381: v334.01,120.02 335.28,118.75 335.28,117.47 336.55,116.2 336.55,114.94 337.82,113.67 D40.24
  Bottom 0.381: v334.01,120.02 330.2,123.83 R56.2
GND  (via drill 0.61)  (1 unrouted)
  Top 1.016: v351.79,104.14 351.79,99.69 J1.3 | SLOT2.2 297.81,97.79 297.81,98.42 298.45,99.06 v298.45,101.6 298.45,109.86 299.08,110.49 299.08,114.3 298.13,115.25 | 298.13,115.25 297.81,115.57 SLOT1.2 | v299.08,133.35 299.08,130.18 298.45,129.54 298.45,115.57 298.13,115.25 | D40.17 330.2,114.94 330.2,113.67 D40.18 330.2,112.39 v330.2,106.05 v330.2,104.14 v330.2,93.98 | D40.19 332.74,114.94 332.74,113.67 D40.20 | IC16.13 325.12,77.47 325.12,78.11 327.66,80.64 327.66,93.34 R18.1 | v304.8,106.05 304.8,102.23 R17.1 | IC17.10 299.72,11.43 299.72,8.26 D2.A | v279.4,24.77 279.4,21.59 IC17.19 279.4,19.05 279.4,15.88 277.5,13.97 277.5,13.34 IC17.1 | v289.56,24.77 289.56,27.3 C25.2 | v274.32,9.53 274.32,13.34 C24.2 | v307.34,71.75 307.34,69.85 IC13.8 307.34,67.31 v307.34,46.99 | v297.18,71.75 297.18,74.93 IC13.13 | v352.43,2.54 v352.43,6.35 | 376.24,26.99 376.56,26.67 376.56,2.54 v375.92,1.91 | 376.24,26.99 v375.92,27.3 | v314.96,3.17 314.96,4.45 D1.A | 376.24,26.99 376.56,27.3 376.56,68.58 v375.29,69.85 v375.29,91.44 | v356.87,50.8 356.87,64.77 358.14,66.04 v358.14,69.85 | v339.09,27.94 339.09,10.79 V-.1 | v248.92,101.6 248.92,98.42 SLOT2.40 | v261.62,101.6 261.62,98.42 SLOT2.30 | v274.32,109.86 274.32,112.39 SLOT1.19 273.69,113.03 273.69,113.67 272.42,114.94 272.42,115.57 SLOT1.22 271.78,116.2 271.78,121.92 274.32,124.46 274.32,130.18 IDE.19 273.69,130.81 273.69,131.44 272.42,132.72 272.42,133.35 IDE.22 271.78,133.99 271.78,135.89 296.55,135.89 297.18,135.25 297.18,133.99 IDE.2 | v267.97,109.86 v267.97,100.33 | SLOT1.40 248.92,116.2 v248.92,118.11 248.92,127.64 248.28,128.27 248.28,128.91 247.01,130.18 v247.01,133.35
  Top 1.016: SLOT1.30 261.62,116.2 v261.62,118.11 v261.62,125.09 | v215.9,71.12 215.9,74.93 IC10.13 215.9,77.47 215.9,112.39 F40.18 215.9,113.67 215.9,114.94 F40.17 215.9,116.2 v215.9,131.44 | v226.06,71.75 226.06,69.85 IC10.8 | v218.44,118.11 218.44,116.2 F40.19 | v267.97,125.73 267.97,120.65 269.24,119.38 269.24,116.2 SLOT1.24 | C5.2 259.08,17.14 259.08,16.51 EXTRESET.4 259.71,13.97 259.71,6.99 259.08,6.35 259.08,3.81 EXTRESET.3 | v236.22,1.91 236.22,4.45 C4.2 | v246.38,1.91 246.38,4.45 J3.2 | X1.5 191.77,10.16 191.77,5.08 X1.G2 | v228.6,15.24 228.6,19.05 IC3.15 | v194.94,15.24 v194.94,10.16 | v245.75,53.98 245.75,55.24 243.84,55.24 241.94,57.15 241.94,57.78 IC11.13 | v251.46,53.98 251.46,52.07 IC11.8 251.46,49.53 251.46,46.35 250.19,45.09 250.19,43.18 v248.92,41.91 248.92,38.73 XESS.52 | v241.3,79.38 241.3,77.47 IC12.13 | v256.54,77.47 v256.54,69.85 256.54,53.98 255.27,52.7 255.27,52.07 254.63,52.07 C15.2 | v215.9,53.34 215.9,57.15 IC9.13 | C13.2 205.74,51.44 v205.74,41.91 205.74,24.77 GND1.1 208.91,19.68 v208.91,13.97 | v185.42,69.85 v185.42,61.59 | v192.41,61.59 v192.41,41.91 | CONFIGSW.18 78.74,75.56 78.74,74.3 CONFIGSW.17 78.74,73.03 78.74,71.75 CONFIGSW.16 78.74,70.48 78.74,69.22 CONFIGSW.15 78.74,67.94 78.74,66.67 CONFIGSW.14 78.74,65.41 78.74,64.14 CONFIGSW.13 78.74,62.87 78.74,61.59 CONFIGSW.12 78.74,60.33 78.74,59.05 CONFIGSW.11 78.74,57.78 78.74,56.52 CONFIGSW.10 80.01,55.88 v80.01,42.55 | v68.58,76.2 68.58,79.38 C7.2 | C40.17 44.45,114.94 44.45,113.67 C40.18 44.45,112.39 v44.45,83.19 | v29.84,81.28 29.84,82.55 30.48,83.19 30.48,85.09 IC1.13
  Top 1.016: v55.88,83.19 55.88,85.09 IC4.13 | v40.64,83.19 40.64,80.01 IC1.8 | v66.04,82.55 66.04,80.01 IC4.8 | v101.6,1.91 101.6,6.99 B40.4 | v35.56,1.91 35.56,6.99 A40.4 | v33.02,43.81 33.02,46.99 IC14.15 | IC14.10 45.72,46.99 45.72,44.45 47.62,42.55 47.62,41.27 IC14.8 48.26,41.91 v48.26,43.81 | v62.23,43.81 62.23,46.99 IC15.15 | v57.15,43.81 57.15,42.55 C20.2 | v77.47,43.81 77.47,41.91 IC15.8 | v139.7,61.59 139.7,64.77 IC7.13 | v149.86,61.59 149.86,59.69 IC7.8 | v116.84,43.81 116.84,41.91 IC18.8 | v129.54,51.44 129.54,49.53 IC2.15 129.54,46.99 v129.54,44.45 | v124.46,51.44 124.46,57.15 IC5.8 124.46,59.69 v124.46,62.23 | v144.78,44.45 144.78,41.91 IC2.8 | v114.3,62.23 114.3,64.77 IC5.13 | v101.6,59.69 101.6,49.53 IC18.15 101.6,46.99 v101.6,43.81 | v91.44,80.01 91.44,76.83 CONFIG.11 91.44,75.56 91.44,74.3 CONFIG.9 91.44,73.03 91.44,71.75 CONFIG.7 91.44,70.48 91.44,69.22 CONFIG.5 91.44,67.94 91.44,66.67 CONFIG.3 91.44,65.41 91.44,64.14 CONFIG.1 91.44,62.87 v91.44,59.69 | v114.3,82.55 114.3,85.09 IC6.13 | v104.14,82.55 104.14,80.64 C8.2 | v124.46,83.19 124.46,80.01 IC6.8 | v140.34,83.19 139.7,83.82 139.7,85.09 IC8.13 | v149.22,83.19 149.22,79.38 IC8.8 | v127,83.19 127,112.39 E40.18 127,113.67 127,114.94 E40.17 127,116.2 v127,128.27 | v27.94,5.71 27.94,41.27 C19.2
  Bottom 1.016: J1.2 346.71,96.52 349.25,96.52 J1.3 | v298.45,101.6 304.17,101.6 R17.1 | v299.08,133.35 297.81,133.35 IDE.2 | D40.20 332.11,113.03 330.83,113.03 D40.18 | v330.2,93.98 328.3,93.98 R18.1 | v304.8,106.05 v330.2,106.05 | v330.2,104.14 v351.79,104.14 367.67,104.14 GND2.1 372.75,100.97 376.56,97.16 376.56,91.44 v375.29,91.44 | C17.2 306.7,13.97 299.72,13.97 IC17.10 299.72,11.43 297.81,9.53 v274.32,9.53 | C24.2 274.95,13.97 276.86,13.97 IC17.1 | v289.56,24.77 v279.4,24.77 | v307.34,71.75 v297.18,71.75 | IC16.8 335.28,69.85 337.19,69.85 C14.2 338.45,69.85 v358.14,69.85 v375.29,69.85 | V-.1 341,6.35 347.98,6.35 J4.11 348.62,6.35 v352.43,6.35 | v352.43,2.54 364.49,2.54 365.12,3.17 368.3,3.17 370.2,1.27 372.75,1.27 J4.13 373.38,1.27 375.92,1.27 v375.92,1.91 | v375.92,27.3 375.92,28.57 J4.14 | IC19.7 325.12,11.43 325.75,10.79 335.92,10.79 V-.1 | v314.96,3.17 334.64,3.17 335.92,4.45 V-.1 | v307.34,46.99 314.96,46.99 316.23,48.26 340.36,48.26 342.9,50.8 v356.87,50.8 | v339.09,27.94 290.19,27.94 C25.2 | IDE.30 262.25,133.35 263.52,133.35 IDE.28 264.8,133.35 266.06,133.35 IDE.26 267.33,133.35 268.61,133.35 IDE.24 269.88,133.35 271.14,133.35 IDE.22 | SLOT1.26 267.33,115.57 268.61,115.57 SLOT1.24 269.88,115.57 271.14,115.57 SLOT1.22 | SLOT2.19 274.32,95.89 273.69,95.89 272.42,97.16 271.78,97.16 SLOT2.22 271.14,97.79 269.88,97.79 SLOT2.24 268.61,97.79 267.33,97.79 SLOT2.26 266.7,98.42 266.7,100.33 | v248.92,101.6 v261.62,101.6 262.89,101.6 264.16,100.33 266.7,100.33 | v274.32,109.86 v267.97,109.86 | v267.97,100.33 266.7,100.33 | v261.62,118.11 v248.92,118.11 v218.44,118.11
  Bottom 1.016: v247.01,133.35 248.28,133.35 IDE.40 | F40.20 217.81,113.03 216.53,113.03 F40.18 | F40.19 217.81,115.57 216.53,115.57 F40.17 | 215.26,71.12 v215.9,71.12 | 215.26,71.12 206.38,71.12 205.74,70.48 C10.2 205.1,69.85 v185.42,69.85 | v226.06,71.75 215.9,71.75 215.26,71.12 | v215.9,131.44 193.04,131.44 192.41,132.08 182.88,132.08 GND4.1 | v267.97,125.73 262.25,125.73 v261.62,125.09 | 236.54,1.59 236.85,1.27 246.38,1.27 | 236.54,1.59 v236.22,1.91 | 246.38,1.27 258.44,1.27 EXTRESET.3 | 246.38,1.27 v246.38,1.91 | v228.6,15.24 224.16,15.24 223.52,14.61 C23.2 222.88,13.97 v208.91,13.97 200.66,13.97 199.39,15.24 RS-232.3 196.85,15.24 v194.94,15.24 | v194.94,10.16 192.41,10.16 X1.5 | 236.54,1.59 236.22,1.27 191.77,1.27 X1.G2 | IC11.8 251.46,52.07 253.37,52.07 C15.2 | v251.46,53.98 v245.75,53.98 | C12.2 286.38,69.85 279.4,69.85 277.5,67.94 252.09,67.94 IC12.8 251.46,69.85 253.37,69.85 C11.2 254.63,69.85 v256.54,69.85 | v241.3,79.38 251.46,79.38 253.37,77.47 v256.54,77.47 | C13.2 205.74,52.7 206.38,53.34 v215.9,53.34 224.79,53.34 226.06,52.07 IC9.8 | X1.G1 191.13,26.04 207.01,26.04 GND1.1 | v248.92,41.91 v205.74,41.91 v192.41,41.91 | v185.42,61.59 v192.41,61.59 | IC4.8 66.04,80.01 67.94,80.01 C7.2 | v68.58,76.2 77.47,76.2 CONFIGSW.18 | C40.18 45.09,113.03 46.35,113.03 C40.20 | C40.19 46.35,115.57 45.09,115.57 C40.17 | C6.2 20.32,80.64 20.95,81.28 v29.84,81.28 39.37,81.28 40.64,80.01 IC1.8 | v40.64,83.19 v44.45,83.19 v55.88,83.19 58.42,83.19 59.05,82.55 v66.04,82.55 | A40.4 35.56,6.99 34.29,5.71 v27.94,5.71 17.14,5.71 LOCKSW.1 | v101.6,1.91 100.97,1.27 36.2,1.27 v35.56,1.91 | C19.2 27.94,42.55 28.57,43.18 29.84,43.18 30.48,43.81 v33.02,43.81 v48.26,43.81 49.53,43.81 51.44,41.91 56.52,41.91 C20.2
  Bottom 1.016: v57.15,43.81 v62.23,43.81 v77.47,43.81 78.74,43.81 v80.01,42.55 80.64,41.91 95.89,41.91 C21.2 96.52,42.55 97.16,43.18 98.42,43.18 99.06,43.81 v101.6,43.81 v116.84,43.81 118.11,43.81 120.02,41.91 123.83,41.91 C22.2 124.46,42.55 126.36,44.45 v129.54,44.45 v144.78,44.45 | v149.86,61.59 v139.7,61.59 139.06,62.23 v124.46,62.23 v114.3,62.23 | C18.2 151.76,59.69 149.86,59.69 IC7.8 | v129.54,51.44 v124.46,51.44 | C16.2 103.5,59.69 v101.6,59.69 v91.44,59.69 | E40.18 127.64,113.03 128.91,113.03 E40.20 | E40.19 128.91,115.57 127.64,115.57 E40.17 | IC8.8 149.86,80.01 151.76,80.01 C9.2 | v91.44,80.01 103.5,80.01 C8.2 | v104.14,82.55 v114.3,82.55 118.75,82.55 119.38,83.19 v124.46,83.19 v127,83.19 v140.34,83.19 v149.22,83.19 | v127,128.27 165.1,128.27 GND3.1
I2C-SCL  (via drill 0.61)
  Top 0.381: SLOT2.27 264.16,95.89 262.89,97.16 262.89,111.12 264.16,112.39 SLOT1.27 | v345.44,39.37 345.44,60.96 342.9,63.5 342.9,88.27 335.28,95.89 v335.28,102.87 | v318.77,102.87 317.5,104.14 v317.5,107.31
  Bottom 0.381: v345.44,39.37 324.49,39.37 323.21,38.1 XESS.23 | v318.77,102.87 v335.28,102.87 | v317.5,107.31 314.96,109.86 304.8,109.86 297.81,116.84 266.06,116.84 265.43,116.2 265.43,113.67 264.16,113.67 SLOT1.27
I2C-SDA  (via drill 0.61)
  Top 0.381: 260.35,111.12 260.35,97.16 261.62,95.89 SLOT2.29 | 260.35,111.12 261.62,112.39 SLOT1.29 | v320.04,45.72 320.04,38.73 XESS.24 | v354.96,46.99 365.12,57.15 v365.12,125.09 | v262.25,135.89 260.35,133.99 260.35,111.12
  Bottom 0.381: v320.04,45.72 321.31,46.99 v354.96,46.99 | v365.12,125.09 354.33,135.89 v262.25,135.89
IDE-CS0#  (via drill 0.61)
  Top 0.381: v288.29,92.71 288.29,87 289.56,85.72 289.56,83.19 XESS.7 | v307.34,92.71 307.34,113.67 303.53,117.47 303.53,130.81 297.18,137.16 252.73,137.16 252.73,132.72 251.46,131.44 IDE.37
  Bottom 0.381: v288.29,92.71 v307.34,92.71
IDE-CS1#  (via drill 0.61)
  Top 0.381: v290.83,93.98 290.83,88.27 292.1,87 292.1,83.19 XESS.8 | v265.43,101.6 265.43,122.56 262.89,125.09 v262.89,128.91
  Bottom 0.381: v290.83,93.98 290.83,101.6 v265.43,101.6 | v262.89,128.91 262.25,129.54 253.37,129.54 252.73,130.18 252.73,132.72 251.46,132.72 IDE.38
IDE-DMACK#  (via drill 0.61)
  Top 0.381: v260.35,39.37 260.35,20.95 255.27,15.88 255.27,12.06 254,10.79 242.57,10.79 242.57,54.61 240.03,57.15 v240.03,128.27
  Bottom 0.381: v260.35,39.37 269.88,39.37 271.14,38.1 XESS.43 | v240.03,128.27 246.38,134.62 257.18,134.62 257.81,133.99 257.81,132.08 259.71,132.08 260.99,130.81 IDE.29
IDE-DMARQ  (via drill 0.61)
  Top 0.381: R12.1 314.96,99.69 314.96,100.97 R17.2 | v265.43,45.72 267.97,48.26 v267.97,55.88 | v297.18,58.42 v297.18,50.8 | v327.66,50.8 328.93,52.07 328.93,69.85 331.47,72.39 331.47,85.72 v330.2,87
  Bottom 0.381: v265.43,45.72 264.8,45.72 257.18,38.1 XESS.49 | v267.97,55.88 270.51,58.42 v297.18,58.42 | v297.18,50.8 v327.66,50.8 | v330.2,87 318.13,99.06 315.6,99.06 R12.1
IDE-IORDY  (via drill 0.61)
  Top 0.381: R15.1 314.96,92.08 316.23,93.34 316.23,94.61 317.5,95.89 R19.1 | v269.24,52.07 269.24,38.73 XESS.44 | v304.8,54.61 306.07,55.88 306.07,87 v307.34,88.27
  Bottom 0.381: v269.24,52.07 270.51,53.34 290.19,53.34 291.46,54.61 v304.8,54.61 | v307.34,88.27 310.51,91.44 314.32,91.44 R15.1
IDE-IRQ  (via drill 0.61)
  Top 0.381: R18.2 317.5,93.34 317.5,92.08 314.96,89.53 R16.1 314.96,88.27 v312.42,85.72
  Bottom 0.381: v312.42,85.72 301.62,85.72 299.72,83.82 281.31,83.82 280.04,82.55 XESS.3
IF0
  Top 0.381: R134.2 52.07,104.78 52.07,112.39 C40.24
IF1
  Top 0.381: R136.2 54.61,123.83 54.61,116.2 C40.25
IF2
  Top 0.381: R138.2 64.77,104.78 64.77,112.39 C40.34
ION
  Top 0.381: R62.2 350.52,123.83 349.25,122.56 349.25,114.94 350.52,113.67 D40.34
IOT
  Top 0.381: R55.2 333.38,124.46 334.64,125.73 336.55,125.73 336.55,117.47 337.82,116.2 D40.23
ISZ
  Top 0.381: R52.2 314.96,123.83 314.96,117.47 313.69,116.2 313.69,114.94 314.96,113.67 D40.6
JMP
  Top 0.381: R59.2 322.58,123.83 322.58,117.47 321.31,116.2 321.31,114.94 322.58,113.67 D40.12
JMS
  Top 0.381: R97.2 320.04,123.83 318.77,122.56 318.77,114.94 320.04,113.67 D40.10
LA
  Top 0.381: B40.18 119.38,8.26 118.11,9.53 118.11,18.41 119.38,19.68 R43.1 119.38,20.95 120.65,22.23 120.65,31.75 123.19,31.75 130.81,39.37 130.81,45.72 132.08,46.99 IC2.14
LCL\  (via drill 0.61)  (1 unrouted)
  Top 0.381: IC9.10 223.52,59.69 224.79,60.96 v224.79,70.48 224.79,72.39 223.52,73.66 223.52,74.93 IC10.10 223.52,77.47 223.52,78.11 224.79,79.38 224.79,84.45 v224.16,85.09 | v245.11,78.11 v245.11,70.48 245.11,63.5 248.92,59.69 IC11.10 | v293.37,59.69 293.37,49.53 295.91,46.99 295.91,15.24 297.18,13.97 IC17.9 | IC1.10 38.1,87.63 38.1,88.9 38.73,89.53 43.18,89.53 43.18,81.28 47.62,76.83 62.23,76.83 62.23,83.82 63.5,85.09 IC4.10 63.5,87.63 v71.12,95.25 | IC5.10 121.92,67.31 121.92,76.2 123.19,77.47 123.19,83.82 121.92,85.09 IC6.10 121.92,87.63 125.73,91.44 v125.73,95.25 | IC7.10 147.32,67.31 146.05,68.58 146.05,83.82 147.32,85.09 IC8.10 147.32,87.63 148.59,88.9 v148.59,102.23
  Bottom 0.381: v224.16,85.09 212.72,96.52 200.03,96.52 198.75,95.25 183.51,95.25 180.97,97.79 179.07,97.79 179.07,99.69 177.8,100.97 SV1.6 | IC13.10 305.44,76.83 306.7,78.11 330.83,78.11 332.11,76.83 IC16.10 332.11,75.56 328.3,71.75 309.25,71.75 307.98,70.48 291.46,70.48 290.83,69.85 290.83,64.77 274.95,64.77 274.32,64.14 274.32,59.69 | v245.11,78.11 247.01,78.11 248.28,76.83 IC12.10 | 274.32,59.69 259.71,59.69 255.91,55.88 252.73,55.88 252.09,56.52 250.82,56.52 249.56,57.78 IC11.10 | 274.32,59.69 v293.37,59.69 | v224.79,70.48 v245.11,70.48 | SV2.6 164.47,101.6 163.83,102.23 v148.59,102.23 132.72,102.23 128.27,97.79 | 128.27,97.79 v125.73,95.25 | v71.12,95.25 73.66,97.79 128.27,97.79
LCLK  (via drill 0.61)  (1 unrouted)
  Top 0.381: IC19.2 311.79,12.06 310.51,12.06 IC19.1 309.88,13.97 304.8,19.05 | 304.8,19.05 303.53,20.32 303.53,57.78 300.99,60.33 300.99,73.66 302.26,74.93 IC13.11 | 304.8,19.05 v304.17,18.41 | IC9.11 220.98,59.69 222.25,60.96 222.25,72.39 220.98,73.66 220.98,74.93 IC10.11 220.98,77.47 220.98,80.64 219.71,81.92 v219.71,102.87 | v243.21,100.97 243.21,93.98 245.11,92.08 245.11,81.92 246.38,80.64 246.38,77.47 IC12.11 | v270.51,8.26 v270.51,60.96 | v59.05,89.53 60.96,87.63 IC4.11 | IC5.11 119.38,67.31 120.65,68.58 120.65,83.82 119.38,85.09 IC6.11 | IC7.11 144.78,67.31 144.15,67.94 144.15,76.83 143.51,77.47 143.51,83.82 144.78,85.09 IC8.11 144.78,87.63 146.05,88.9 v146.05,105.41
  Bottom 0.381: IC17.16 287.65,19.68 288.93,18.41 290.19,18.41 291.46,19.68 IC17.14 292.74,19.68 294,18.41 v304.17,18.41 | IC13.11 302.89,75.56 305.44,73.03 327.02,73.03 329.56,75.56 IC16.11 | IC9.11 221.62,57.78 222.88,56.52 224.79,56.52 226.06,55.24 243.21,55.24 245.75,57.78 IC11.11 247.01,59.05 248.92,60.96 v270.51,60.96 | v243.21,100.97 241.3,102.87 v219.71,102.87 182.25,102.87 180.97,104.14 SV1.3 | v270.51,8.26 298.45,8.26 301.62,11.43 308.61,11.43 309.25,12.06 IC19.1 | v59.05,89.53 53.34,95.25 44.45,95.25 36.2,87 IC1.11 | v146.05,105.41 165.74,105.41 167,104.14 SV2.3 | IC8.11 144.15,85.72 142.88,84.45 121.28,84.45 120.02,85.72 IC6.11 118.75,85.72 116.84,83.82 63.5,83.82 61.59,85.72 IC4.11
LEFT  (via drill 0.61)  (1 unrouted)
  Top 0.381: v205.1,67.94 205.1,66.67 212.72,59.05 IC9.14 | v186.69,68.58 186.69,78.74 185.42,80.01 185.42,98.42 184.15,99.69 v184.15,106.68 | v165.1,87 166.37,88.27 166.37,104.78 167.64,106.05 SV2.1
  Bottom 0.381: v205.1,67.94 204.47,68.58 v186.69,68.58 | v184.15,106.68 180.97,106.68 SV1.1 | v165.1,87 150.5,87 IC8.9
LINK
  Top 0.381: R139.2 57.15,104.78 57.15,112.39 C40.28
LSER  (via drill 0.61)  (1 unrouted)
  Top 0.381: v281.94,15.88 281.94,19.05 IC17.18 | v320.68,15.88 323.85,19.05 v323.85,54.61 | v358.77,57.15 363.86,62.23 v363.86,128.27 | v187.32,133.35 184.15,130.18 184.15,112.39 179.07,107.31 179.07,98.42 180.34,97.16 SV1.9
  Bottom 0.381: v320.68,15.88 v281.94,15.88 | v323.85,54.61 326.39,57.15 v358.77,57.15 | v363.86,128.27 354.96,137.16 191.13,137.16 v187.32,133.35 | IC1.14 28.57,87 34.29,92.71 40.64,92.71 44.45,96.52 67.94,96.52 73.66,90.81 161.29,90.81 167,96.52 SV2.9
MA0
  Top 0.381: R99.2 109.22,123.83 109.22,116.2 E40.3
MA1
  Top 0.381: R104.2 114.3,104.78 114.3,112.39 E40.8
MA2
  Top 0.381: R109.2 121.92,123.83 121.92,116.2 E40.13
MA3
  Top 0.381: R114.2 132.08,104.78 132.08,112.39 E40.22
MA4
  Top 0.381: R119.2 139.7,123.83 139.7,116.2 E40.27
MA5
  Top 0.381: R124.2 144.78,104.78 144.78,112.39 E40.32
MA6
  Top 0.381: R68.2 198.12,123.83 198.12,116.2 F40.3
MA7
  Top 0.381: R73.2 203.2,104.78 203.2,112.39 F40.8
MA8
  Top 0.381: R78.2 210.82,123.83 210.82,116.2 F40.13
MA9
  Top 0.381: R83.2 220.98,104.78 220.98,112.39 F40.22
MA10
  Top 0.381: R88.2 228.6,123.83 228.6,116.2 F40.27
MA11
  Top 0.381: R93.2 233.68,104.78 233.68,112.39 F40.32
MASTER-RESET#  (via drill 0.61)
  Top 0.381: IDE.1 297.18,130.18 297.18,117.47 295.91,116.2 295.91,114.94 297.18,113.67 SLOT1.1 297.18,112.39 297.18,99.69 295.91,98.42 295.91,97.16 297.18,95.89 SLOT2.1 297.18,94.61 v297.18,91.44 | v285.75,36.83 285.75,10.79 283.85,10.79 282.57,12.06 IC17.3
  Bottom 0.381: v285.75,36.83 348.62,36.83 349.25,37.47 350.52,37.47 351.79,36.2 353.06,36.2 376.56,59.69 376.56,84.45 343.54,84.45 341,81.92 337.19,81.92 333.38,85.72 325.75,85.72 318.77,92.71 309.25,92.71 306.7,90.17 299.08,90.17 297.81,91.44 v297.18,91.44
MB0
  Top 0.381: R100.2 111.76,123.83 111.76,116.2 E40.5
MB1
  Top 0.381: R105.2 111.76,104.78 111.76,112.39 E40.6
MB2
  Top 0.381: R110.2 124.46,123.83 124.46,116.2 E40.15
MB3
  Top 0.381: R115.2 124.46,104.78 124.46,112.39 E40.16
MB4
  Top 0.381: R120.2 142.24,123.83 142.24,116.2 E40.29
MB5
  Top 0.381: R125.2 142.24,104.78 142.24,112.39 E40.30
MB6
  Top 0.381: R69.2 200.66,123.83 200.66,116.2 F40.5
MB7
  Top 0.381: R74.2 200.66,104.78 200.66,112.39 F40.6
MB8
  Top 0.381: R79.2 213.36,123.83 213.36,116.2 F40.15
MB9
  Top 0.381: R84.2 213.36,104.78 213.36,112.39 F40.16
MB10
  Top 0.381: R89.2 231.14,123.83 231.14,116.2 F40.29
MB11
  Top 0.381: R94.2 231.14,104.78 231.14,112.39 F40.30
MQ0
  Top 0.381: R102.2 116.84,123.83 116.84,116.2 E40.9
MQ1
  Top 0.381: R107.2 106.68,104.78 106.68,112.39 E40.2
MQ2
  Top 0.381: R112.2 134.62,123.83 134.62,116.2 E40.23
MQ3
  Top 0.381: R117.2 119.38,104.78 119.38,112.39 E40.12
MQ4
  Top 0.381: R122.2 147.32,123.83 147.32,116.2 E40.33
MQ5
  Top 0.381: R127.2 137.16,104.78 137.16,112.39 E40.26
MQ6
  Top 0.381: R71.2 205.74,123.83 205.74,116.2 F40.9
MQ7
  Top 0.381: R76.2 195.58,104.78 195.58,112.39 F40.2
MQ8
  Top 0.381: R81.2 223.52,123.83 223.52,116.2 F40.23
MQ9
  Top 0.381: R86.2 208.28,104.78 208.28,112.39 F40.12
MQ10
  Top 0.381: R91.2 236.22,123.83 236.22,116.2 F40.33
MQ11
  Top 0.381: R96.2 226.06,104.78 226.06,112.39 F40.26
N$1
  Bottom 0.381: IC14.9 48.9,48.9 50.16,50.16 73.03,50.16 74.3,48.9 IC15.10
N$2
  Bottom 0.381: IC15.9 78.11,47.62 80.01,45.72 139.7,45.72 141.6,47.62 IC2.10
N$3
  Bottom 0.381: IC18.10 114.94,48.9 116.2,50.16 142.88,50.16 144.15,48.9 IC2.9
N$4  (via drill 0.61)
  Top 0.381: v113.03,64.14 113.03,80.01 111.76,81.28 111.76,85.09 IC6.14
  Bottom 0.381: v113.03,64.14 115.57,64.14 115.57,67.31 116.2,67.94 122.56,67.94 123.83,66.67 IC5.9
N$5
  Top 0.381: IC3.10 241.3,21.59 241.3,27.3 R3.2
N$6
  Top 0.381: IC3.11 238.76,21.59 238.76,24.77 R1.2
N$7  (via drill 0.61)
  Top 0.381: v298.45,47.62 298.45,37.47 302.26,33.66 302.26,17.14 311.79,7.62 314.32,7.62 R2.2 | v248.92,48.26 245.11,44.45 245.11,22.86 243.84,21.59 IC3.9
  Bottom 0.381: v298.45,47.62 297.81,48.26 v248.92,48.26
N$8
  Top 0.381: C1.2 228.6,8.26 228.6,11.43 IC3.2
N$9
  Top 0.381: C2.2 231.14,5.71 231.14,11.43 IC3.3
N$10
  Bottom 0.381: IC1.9 41.27,87 42.55,88.27 51.44,88.27 52.7,87 IC4.14
N$11
  Top 0.381: C2.1 226.06,5.71 226.06,11.43 IC3.1
N$12
  Top 0.381: C4.1 241.3,5.71 240.03,6.99 240.03,10.16 238.76,11.43 IC3.6
N$13  (via drill 0.61)
  Top 0.381: v150.5,71.12 150.5,67.94 149.86,67.31 IC7.9 | v139.06,72.39 138.43,73.03 138.43,80.01 137.16,81.28 137.16,85.09 IC8.14
  Bottom 0.381: v150.5,71.12 149.22,72.39 v139.06,72.39
N$14  (via drill 0.61)
  Top 0.381: v137.16,71.12 125.73,82.55 125.73,83.82 124.46,85.09 IC6.9
  Bottom 0.381: v137.16,71.12 137.16,67.31 IC7.14
N$15  (via drill 0.61)
  Top 0.381: v238.76,71.75 238.76,74.93 IC12.14 | v251.46,71.75 252.73,70.48 252.73,60.96 251.46,59.69 IC11.9
  Bottom 0.381: v251.46,71.75 v238.76,71.75
N$16  (via drill 0.61)
  Top 0.381: v228.6,62.87 v228.6,75.56
  Bottom 0.381: v228.6,62.87 234.31,62.87 238.12,59.05 IC11.14 | v228.6,75.56 226.69,75.56 IC10.9
N$17
  Bottom 0.381: IC13.9 307.98,75.56 309.25,74.3 320.68,74.3 321.94,75.56 IC16.14
N$18
  Top 0.381: C3.1 233.68,8.26 233.68,11.43 IC3.4
N$19
  Top 0.381: IC9.9 225.43,57.78 224.16,56.52 217.17,56.52 217.17,59.69 214.63,62.23 214.63,72.39 213.36,73.66 213.36,74.93 IC10.14
N$20
  Top 0.381: C3.2 238.76,8.26 236.22,10.79 236.22,11.43 IC3.5
N$21  (via drill 0.61)
  Top 0.381: v76.2,74.93 66.04,85.09 IC4.9 | v107.31,74.93 111.76,70.48 111.76,67.31 IC5.14
  Bottom 0.381: v76.2,74.93 v107.31,74.93
N$22
  Top 0.381: IC19.5 320.68,12.06 323.21,9.53 331.47,9.53 331.47,64.77 334.01,67.31 334.01,69.85 335.28,71.12 335.28,74.93 IC16.9
N$23  (via drill 0.61)
  Top 0.381: v254.63,71.75 251.46,74.93 IC12.9 | v294.64,71.75 294.64,74.93 IC13.14
  Bottom 0.381: v254.63,71.75 v294.64,71.75
N$24  (via drill 0.61)
  Top 0.381: v295.91,78.11 v295.91,85.09 | v322.58,87 v322.58,111.12 | v321.31,118.11 v321.31,133.35
  Bottom 0.381: v295.91,78.11 294,78.11 292.74,76.83 IC13.15 | v295.91,85.09 297.81,87 v322.58,87 | v322.58,111.12 321.31,112.39 v321.31,118.11 | v321.31,133.35 319.4,133.35 318.13,134.62 R51.1
N$25  (via drill 0.61)
  Top 0.381: v287.02,62.23 v287.02,66.04 | v337.82,60.96 339.09,62.23 339.09,90.81 334.01,95.89 v334.01,111.12 | v316.23,123.19 316.23,132.72 314.96,133.99 R52.1
  Bottom 0.381: v287.02,66.04 288.93,67.94 IC13.1 | v287.02,62.23 288.29,60.96 v337.82,60.96 | v334.01,111.12 333.38,111.76 327.02,111.76 326.39,112.39 326.39,118.75 325.75,118.75 321.31,123.19 v316.23,123.19
N$26  (via drill 0.61)
  Top 0.381: v314.96,65.41 314.96,80.64 316.23,81.92 316.23,83.82 320.04,87.63 v320.04,111.12 | v313.69,118.11 313.69,132.72 312.42,133.99 R53.1
  Bottom 0.381: v314.96,65.41 295.27,65.41 292.74,67.94 IC13.2 | v320.04,111.12 318.77,112.39 318.77,118.11 v313.69,118.11
N$27
  Bottom 0.381: IC19.3 315.6,12.06 316.87,12.06 IC19.4
N$28
  Top 0.381: R11.1 292.1,5.71 292.1,11.43 IC17.7
N$29  (via drill 0.61)
  Top 0.381: v261.62,109.86 261.62,106.05 R21.2
  Bottom 0.381: v261.62,109.86 259.08,112.39 SLOT1.31
N$30
  Top 0.381: R22.2 259.08,104.78 259.08,99.69 257.81,98.42 257.81,97.16 259.08,95.89 SLOT2.31
N$31  (via drill 0.61)
  Top 0.381: C5.1 264.16,17.14 264.16,16.51 EXTRESET.2 263.52,13.97 263.52,3.81 EXTRESET.1 | R20.2 266.06,17.78 264.8,17.78 C5.1 | v264.16,26.04 264.16,18.41 C5.1 | v284.48,26.04 284.48,21.59 IC17.17
  Bottom 0.381: 269.88,26.67 269.24,26.04 v264.16,26.04 | 269.88,26.67 271.14,27.94 R23.2 | v284.48,26.04 283.85,26.67 269.88,26.67
N$32  (via drill 0.61)
  Top 0.381: v316.23,66.67 316.23,79.38 318.77,81.92 318.77,85.09 321.31,87.63 v321.31,107.31 | v311.15,118.11 311.15,132.72 309.88,133.99 R54.1
  Bottom 0.381: v316.23,66.67 296.55,66.67 295.27,67.94 IC13.3 | v321.31,107.31 316.23,112.39 316.23,116.84 312.42,116.84 v311.15,118.11
N$33  (via drill 0.61)
  Top 0.381: v298.45,58.42 298.45,66.04 297.18,67.31 IC13.4 | v358.14,58.42 362.58,62.87 362.58,125.73 351.15,137.16 332.74,137.16 332.74,135.25 R55.1
  Bottom 0.381: v298.45,58.42 v358.14,58.42
N$34  (via drill 0.61)
  Top 0.381: v302.26,93.98 302.26,90.81 303.53,89.53 303.53,81.92 300.99,79.38 300.99,74.93 299.72,73.66 299.72,69.85 IC13.5 | v309.88,102.87 308.61,104.14 308.61,113.67 307.34,114.94 307.34,133.99 309.25,135.89 330.2,135.89 330.2,135.25 R56.1
  Bottom 0.381: v302.26,93.98 303.53,95.25 308.61,95.25 309.88,96.52 v309.88,102.87
N$35  (via drill 0.61)
  Top 0.381: v303.53,59.69 303.53,66.04 302.26,67.31 IC13.6 | v346.71,59.69 353.06,66.04 v353.06,123.83 | v327.66,130.81 327.66,133.99 R57.1
  Bottom 0.381: v303.53,59.69 v346.71,59.69 | v353.06,123.83 346.07,130.81 v327.66,130.81
N$36  (via drill 0.61)
  Top 0.381: v304.8,64.14 304.8,67.31 IC13.7 | v344.17,64.14 344.17,92.08 342.9,93.34 342.9,108.58 339.09,112.39 v339.09,125.73 | v325.75,129.54 325.12,130.18 325.12,133.99 R58.1
  Bottom 0.381: v304.8,64.14 v344.17,64.14 | v339.09,125.73 335.28,129.54 v325.75,129.54
N$37
  Top 0.381: IC16.15 320.04,77.47 321.31,78.74 321.31,83.82 323.85,86.36 323.85,132.72 322.58,133.99 R59.1
N$38  (via drill 0.61)
  Top 0.381: v355.6,73.66 358.14,76.2 358.14,122.56 346.07,134.62 R60.1
  Bottom 0.381: v355.6,73.66 334.01,73.66 330.83,70.48 319.4,70.48 318.13,69.22 IC16.1
N$39  (via drill 0.61)
  Top 0.381: v359.41,65.41 360.05,66.04 360.05,121.92 347.98,133.99 R61.1
  Bottom 0.381: v359.41,65.41 323.21,65.41 320.68,67.94 IC16.2
N$40  (via drill 0.61)
  Top 0.381: v361.31,66.67 361.31,125.73 352.43,134.62 351.15,134.62 R62.1
  Bottom 0.381: v361.31,66.67 324.49,66.67 323.21,67.94 IC16.3
N$41  (via drill 0.61)
  Top 0.381: v326.39,107.31 326.39,87.63 323.85,85.09 323.85,71.12 325.12,69.85 IC16.4 | v346.71,127 342.9,130.81 342.9,133.99 R63.1
  Bottom 0.381: v326.39,107.31 328.3,109.22 343.54,109.22 346.71,112.39 v346.71,127
N$42  (via drill 0.61)
  Top 0.381: v328.93,95.25 328.93,71.12 327.66,69.85 IC16.5 | v349.25,101.6 350.52,102.87 350.52,111.12 351.79,112.39 351.79,125.09 346.07,130.81 344.17,130.81 344.17,135.25 343.54,135.89 340.36,135.89 340.36,135.25 R64.1
  Bottom 0.381: v328.93,95.25 335.28,101.6 v349.25,101.6
N$43  (via drill 0.61)
  Top 0.381: v346.71,72.39 347.98,73.66 347.98,106.05 341.63,112.39 341.63,130.18 337.82,133.99 R65.1
  Bottom 0.381: v346.71,72.39 334.01,72.39 330.83,69.22 IC16.6
N$44
  Top 0.381: IC16.7 332.74,69.85 334.01,71.12 334.01,85.09 331.47,87.63 331.47,130.18 335.28,133.99 R66.1
N$45  (via drill 0.61)
  Top 0.381: v196.22,81.92 196.22,92.71 196.85,93.34 196.85,132.72 195.58,133.99 R67.1
  Bottom 0.381: v196.22,81.92 176.53,81.92 176.53,74.93 188.59,62.87 193.04,62.87 195.58,60.33 208.91,60.33 210.19,59.05 IC9.15
N$46  (via drill 0.61)
  Top 0.381: v191.13,50.8 189.23,52.7 v189.23,133.35
  Bottom 0.381: v191.13,50.8 207.65,50.8 IC9.1 | v189.23,133.35 196.22,133.35 197.49,134.62 R68.1
N$47  (via drill 0.61)
  Top 0.381: v202.56,62.87 202.56,75.56 201.93,76.2 201.93,132.72 200.66,133.99 R69.1 | v207.65,61.59 209.55,59.69 209.55,53.34 210.82,52.07 IC9.2
  Bottom 0.381: v202.56,62.87 203.84,61.59 v207.65,61.59
N$48  (via drill 0.61)
  Top 0.381: v207.01,44.45 212.72,50.16 IC9.3 | v182.88,56.52 v182.88,104.14 | v199.39,121.92 199.39,135.25 200.03,135.89 203.2,135.89 203.2,135.25 R70.1
  Bottom 0.381: v207.01,44.45 194.94,44.45 v182.88,56.52 | v182.88,104.14 184.15,105.41 184.78,105.41 185.42,106.05 185.42,113.67 190.5,113.67 198.75,121.92 v199.39,121.92
N$49  (via drill 0.61)
  Top 0.381: v205.1,78.11 205.1,79.38 204.47,80.01 204.47,132.72 205.74,133.99 R71.1 | v201.29,59.05 v201.29,74.93 | v210.82,55.88 215.26,51.44 IC9.4
  Bottom 0.381: v205.1,78.11 201.93,74.93 v201.29,74.93 | v201.29,59.05 204.47,55.88 v210.82,55.88
N$50  (via drill 0.61)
